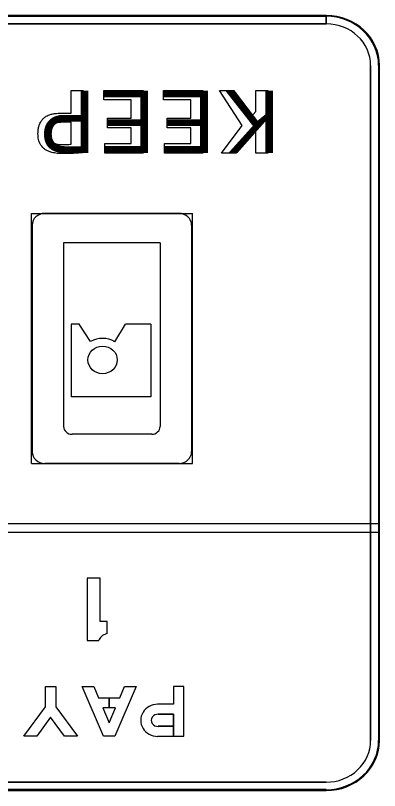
# Model space of a CAD drawing. Extents: x -102643 to -98250, y 54554 to 62384.
# Drawn here: x -101875 to -101631, y 61400 to 61919 of the extents above; entities that cross this region are included whole.
import ezdxf

# ---------------------------------------------------------------- set-up
doc = ezdxf.new("R2010")
doc.units = 0
for name, color, linetype in [('GSBWFill', 7, 'Continuous'), ('GSColorFill', 7, 'Continuous'), ('GSOutline', 7, 'Continuous'), ('SignPanel', 7, 'Continuous')]:
    doc.layers.add(name, color=color, linetype=linetype)

msp = doc.modelspace()

# ---------------------------------------------------------------- linework, layer by layer
at = {"layer": 'GSBWFill'}
for p, q in [((-101666.66, 61919), (-102149.4, 61919)), ((-101666.66, 61913.42), (-101666.66, 61919)), ((-101666.6, 61919), (-101666.6, 61913.42)), ((-102149.4, 61913.42), (-101666.66, 61913.42)), ((-101636.79, 61885.49), (-101636.79, 61433.02)), ((-101630.83, 61433.02), (-101630.83, 61885.49)), ((-101666.6, 61405.09), (-102149.4, 61405.09)), ((-102149.4, 61399.51), (-101666.6, 61399.51))]:
    msp.add_line(p, q, dxfattribs=at)
for centre, major_axis, start_param, end_param in [((-101666.6, 61885.49), (-35.76, 0), 3.141593, 4.712389), ((-101666.6, 61885.49), (-29.8, 0), 3.141593, 4.712389), ((-101666.6, 61433.02), (-35.76, 0), 1.570796, 3.141593), ((-101666.6, 61433.02), (-29.8, 0), 1.570796, 3.141593)]:
    msp.add_ellipse(centre, major_axis=major_axis, ratio=0.937161, start_param=start_param, end_param=end_param, dxfattribs=at)
at = {"layer": 'GSColorFill'}
for p, q in [((-101666.6, 61919), (-102149.4, 61919)), ((-101630.83, 61433.02), (-101630.83, 61885.49)), ((-102149.4, 61399.51), (-101666.6, 61399.51))]:
    msp.add_line(p, q, dxfattribs=at)
for centre, start_param, end_param in [((-101666.6, 61885.49), 3.141593, 4.712389), ((-101666.6, 61433.02), 1.570796, 3.141593)]:
    msp.add_ellipse(centre, major_axis=(-35.76, 0), ratio=0.937161, start_param=start_param, end_param=end_param, dxfattribs=at)
at = {"layer": 'GSOutline'}
for p, q in [((-101666.6, 61919), (-102149.4, 61919)), ((-101666.6, 61913.42), (-102149.4, 61913.42)), ((-101636.79, 61433.02), (-101636.79, 61885.49)), ((-101630.83, 61433.02), (-101630.83, 61885.49)), ((-102149.4, 61405.09), (-101666.6, 61405.09)), ((-102149.4, 61399.51), (-101666.6, 61399.51))]:
    msp.add_line(p, q, dxfattribs=at)
for centre, major_axis, start_param, end_param in [((-101666.6, 61885.49), (-35.76, 0), 3.141593, 4.712389), ((-101666.6, 61885.49), (-29.8, 0), 3.141593, 4.712389), ((-101666.6, 61433.02), (-35.76, 0), 1.570796, 3.141593), ((-101666.6, 61433.02), (-29.8, 0), 1.570796, 3.141593)]:
    msp.add_ellipse(centre, major_axis=major_axis, ratio=0.937161, start_param=start_param, end_param=end_param, dxfattribs=at)
at = {"layer": 'SignPanel'}
for p, q in [((-101666.66, 61919), (-102149.4, 61919)), ((-101666.6, 61919), (-102149.4, 61919)), ((-101666.66, 61913.42), (-101666.66, 61919)), ((-101666.6, 61919), (-101666.6, 61913.42)), ((-101666.6, 61919), (-101666.6, 61918.45)), ((-101666.6, 61918.45), (-101666.6, 61919)), ((-102149.4, 61918.45), (-101666.6, 61918.45)), ((-102149.4, 61913.42), (-101666.66, 61913.42)), ((-101636.79, 61885.49), (-101636.79, 61433.02)), ((-101631.43, 61885.49), (-101631.43, 61433.02)), ((-101630.83, 61433.02), (-101630.83, 61885.49)), ((-101630.83, 61433.02), (-101630.83, 61885.49)), ((-101864.48, 61618.76), (-101864.48, 61786.34)), ((-101864.48, 61786.34), (-101756.44, 61786.34)), ((-101765.4, 61786.34), (-101855.52, 61786.34)), ((-101756.44, 61618.76), (-101756.44, 61786.34)), ((-101863.97, 61778.45), (-101863.97, 61626.65)), ((-101756.96, 61778.45), (-101756.96, 61626.65)), ((-101778.08, 61766.61), (-101842.84, 61766.61)), ((-101842.84, 61766.61), (-101842.84, 61643.53)), ((-101778.08, 61766.61), (-101778.08, 61643.53)), ((-101832.18, 61712.04), (-101837.82, 61712.04)), ((-101837.82, 61712.04), (-101837.82, 61663.34)), ((-101824.76, 61700.44), (-101832.32, 61712.02)), ((-101808.47, 61700.34), (-101801.21, 61712.04)), ((-101784.31, 61712.04), (-101801.21, 61712.04)), ((-101784.31, 61712.04), (-101784.31, 61663.34)), ((-101784.31, 61663.34), (-101837.82, 61663.34)), ((-101783.71, 61638.27), (-101837.21, 61638.27)), ((-101864.48, 61618.76), (-101756.44, 61618.76)), ((-101765.4, 61618.76), (-101855.52, 61618.76)), ((-101630.83, 61578.26), (-102185.16, 61578.26)), ((-101630.83, 61578.26), (-102185.16, 61578.26)), ((-101630.83, 61578.26), (-102185.16, 61578.26)), ((-101630.83, 61572.67), (-101630.83, 61578.26)), ((-101630.83, 61572.67), (-101630.83, 61578.26)), ((-101630.83, 61572.67), (-101630.83, 61578.26)), ((-102185.16, 61572.67), (-101630.83, 61572.67)), ((-102185.16, 61572.67), (-101630.83, 61572.67)), ((-102185.16, 61572.67), (-101630.83, 61572.67)), ((-101769.14, 61457.29), (-101779.75, 61457.29)), ((-101769.14, 61450.59), (-101779.38, 61450.59)), ((-101666.6, 61405.09), (-102149.4, 61405.09)), ((-101666.6, 61400.07), (-102149.4, 61400.07)), ((-102149.4, 61399.51), (-101666.6, 61399.51)), ((-102149.4, 61399.51), (-101666.6, 61399.51))]:
    msp.add_line(p, q, dxfattribs=at)
for points in [[(-101845.32, 61853.46), (-101837.7, 61853.46), (-101837.7, 61868.73), (-101829.66, 61868.73), (-101829.66, 61827.1)], [(-101789.56, 61868.73), (-101789.56, 61826.83), (-101815.15, 61826.83), (-101815.15, 61833.25), (-101797.6, 61833.25), (-101797.6, 61843.79), (-101813.46, 61843.79), (-101813.46, 61850.25), (-101797.6, 61850.25), (-101797.6, 61862.47), (-101815.83, 61862.47), (-101815.83, 61868.73), (-101789.56, 61868.73)], [(-101749.46, 61868.73), (-101749.46, 61826.83), (-101775.05, 61826.83), (-101775.05, 61833.25), (-101757.5, 61833.25), (-101757.5, 61843.79), (-101773.36, 61843.79), (-101773.36, 61850.25), (-101757.5, 61850.25), (-101757.5, 61862.47), (-101775.73, 61862.47), (-101775.73, 61868.73), (-101749.46, 61868.73)], [(-101728.55, 61868.73), (-101717.32, 61850.63), (-101713.74, 61854.74), (-101713.83, 61868.73), (-101705.79, 61868.73), (-101705.79, 61826.83), (-101713.83, 61826.83), (-101713.74, 61845.31), (-101714.01, 61845.31), (-101727.21, 61826.83), (-101736.93, 61826.83), (-101722.96, 61845.23), (-101738.27, 61868.73), (-101728.55, 61868.73)], [(-101837.7, 61832.74), (-101837.7, 61847.4), (-101843.92, 61847.4)], [(-101813.64, 61504.72), (-101813.64, 61512.71), (-101818.23, 61512.71), (-101818.23, 61541.95), (-101827.05, 61541.95), (-101827.05, 61500.05), (-101819.29, 61500.05)], [(-101813.64, 61504.72), (-101813.64, 61512.71), (-101818.23, 61512.71), (-101818.23, 61541.95), (-101827.05, 61541.95), (-101827.05, 61500.05), (-101819.29, 61500.05)], [(-101813.64, 61504.72), (-101813.64, 61512.71), (-101818.23, 61512.71), (-101818.23, 61541.95), (-101827.05, 61541.95), (-101827.05, 61500.05), (-101819.29, 61500.05)], [(-101779.75, 61435.82), (-101762.08, 61435.82), (-101762.08, 61469.33), (-101769.14, 61469.33), (-101769.14, 61457.29)], [(-101762.08, 61435.82), (-101762.08, 61469.33), (-101769.14, 61469.33), (-101769.14, 61457.29), (-101779.75, 61457.29)], [(-101762.08, 61435.82), (-101762.08, 61469.33), (-101769.14, 61469.33), (-101769.14, 61457.29), (-101779.75, 61457.29)], [(-101779.38, 61442.52), (-101769.14, 61442.52), (-101769.14, 61450.59)], [(-101779.38, 61450.59), (-101769.14, 61450.59), (-101769.14, 61435.82), (-101762.08, 61435.82)], [(-101779.38, 61450.59), (-101769.14, 61450.59), (-101769.14, 61435.82), (-101762.08, 61435.82)], [(-101779.75, 61435.82), (-101769.14, 61435.82), (-101769.14, 61442.52), (-101779.38, 61442.52)], [(-101779.75, 61435.82), (-101769.14, 61435.82), (-101769.14, 61442.52), (-101779.38, 61442.52)]]:
    msp.add_lwpolyline(points, dxfattribs=at)
for points in [[(-101855.1, 61469.33), (-101847.95, 61469.33), (-101847.95, 61455.59), (-101833.47, 61435.82), (-101842.14, 61435.82), (-101851.53, 61448.63), (-101860.91, 61435.82), (-101869.59, 61435.82), (-101855.1, 61455.59)], [(-101855.1, 61469.33), (-101847.95, 61469.33), (-101847.95, 61455.59), (-101833.47, 61435.82), (-101842.14, 61435.82), (-101851.53, 61448.63), (-101860.91, 61435.82), (-101869.59, 61435.82), (-101855.1, 61455.59)], [(-101855.1, 61469.33), (-101847.95, 61469.33), (-101847.95, 61455.59), (-101833.47, 61435.82), (-101842.14, 61435.82), (-101851.53, 61448.63), (-101860.91, 61435.82), (-101869.59, 61435.82), (-101855.1, 61455.59)], [(-101819.35, 61461.62), (-101805.17, 61461.62), (-101801.9, 61469.33), (-101794.2, 61469.33), (-101808.41, 61435.82), (-101816.11, 61435.82), (-101830.32, 61469.33), (-101822.62, 61469.33)], [(-101812.26, 61454.92), (-101812.26, 61461.62), (-101805.17, 61461.62), (-101801.9, 61469.33), (-101794.2, 61469.33), (-101808.41, 61435.82), (-101816.11, 61435.82), (-101830.32, 61469.33), (-101822.62, 61469.33), (-101819.35, 61461.62), (-101812.26, 61461.62), (-101812.26, 61454.92), (-101816.51, 61454.92), (-101812.26, 61444.89), (-101808.01, 61454.92)], [(-101812.26, 61454.92), (-101812.26, 61461.62), (-101805.17, 61461.62), (-101801.9, 61469.33), (-101794.2, 61469.33), (-101808.41, 61435.82), (-101816.11, 61435.82), (-101830.32, 61469.33), (-101822.62, 61469.33), (-101819.35, 61461.62), (-101812.26, 61461.62), (-101812.26, 61454.92), (-101816.51, 61454.92), (-101812.26, 61444.89), (-101808.01, 61454.92)], [(-101808.01, 61454.92), (-101816.51, 61454.92), (-101812.26, 61444.89)]]:
    msp.add_lwpolyline(points, close=True, dxfattribs=at)
for centre, major_axis, ratio, start_param, end_param in [((-101666.6, 61885.49), (-35.76, 0), 0.937161, 3.141593, 4.712389), ((-101666.6, 61885.49), (-35.76, 0), 0.937161, 3.141593, 4.712389), ((-101666.6, 61885.49), (-35.17, 0), 0.937161, 3.141593, 4.712389), ((-101666.6, 61885.49), (-29.8, 0), 0.937161, 3.141593, 4.712389), ((-101855.52, 61778.45), (-8.45, 0), 0.933944, 4.712389, 6.283185), ((-101765.4, 61778.45), (8.45, 0), 0.933944, 0, 1.570796), ((-101816.7, 61688.09), (-15.49, 0), 0.933944, 4.152074, 5.259887), ((-101837.21, 61643.54), (5.63, 0), 0.933944, 3.141593, 4.712389), ((-101783.71, 61643.54), (5.63, 0), 0.933944, 4.712389, 6.283185), ((-101855.52, 61626.65), (8.45, 0), 0.933944, 3.141593, 4.712389), ((-101765.4, 61626.65), (8.45, 0), 0.933944, 4.712389, 6.283185), ((-101811.8, 61497.43), (-7.99, 0), 0.937165, 5.230245, 5.516697), ((-101811.8, 61497.43), (-7.99, 0), 0.937165, 5.230245, 5.516697), ((-101811.8, 61497.43), (-7.99, 0), 0.937165, 5.230245, 5.516697), ((-101811.8, 61497.43), (-7.99, 0), 0.937165, 4.943792, 5.230245), ((-101811.8, 61497.43), (-7.99, 0), 0.937165, 4.943792, 5.230245), ((-101811.8, 61497.43), (-7.99, 0), 0.937165, 4.943792, 5.230245), ((-101811.8, 61497.43), (-7.99, 0), 0.937165, 5.720992, 5.925287), ((-101811.8, 61497.43), (-7.99, 0), 0.937165, 5.720992, 5.925287), ((-101811.8, 61497.43), (-7.99, 0), 0.937165, 5.720992, 5.925287), ((-101811.8, 61497.43), (-7.99, 0), 0.937165, 5.516697, 5.720992), ((-101811.8, 61497.43), (-7.99, 0), 0.937165, 5.516697, 5.720992), ((-101811.8, 61497.43), (-7.99, 0), 0.937165, 5.516697, 5.720992), ((-101779.76, 61446.55), (-11.3, 0), 0.950592, 4.711784, 7.854587), ((-101779.76, 61446.55), (-11.3, 0), 0.950592, 4.711784, 7.854587), ((-101779.76, 61446.55), (-11.3, 0), 0.950592, 4.711784, 7.854587), ((-101779.74, 61446.55), (-4.26, 0), 0.950592, 4.627407, 7.938964), ((-101779.74, 61446.55), (-4.26, 0), 0.950592, 4.627407, 7.938964), ((-101779.74, 61446.55), (-4.26, 0), 0.950592, 4.627407, 7.938964), ((-101666.6, 61433.02), (-35.76, 0), 0.937161, 1.570796, 3.141593), ((-101666.6, 61433.02), (-29.8, 0), 0.937161, 1.570796, 3.141593), ((-101666.6, 61433.02), (-35.76, 0), 0.937161, 1.570796, 3.141593), ((-101666.6, 61433.02), (-35.17, 0), 0.937161, 1.570796, 3.141593)]:
    msp.add_ellipse(centre, major_axis=major_axis, ratio=ratio, start_param=start_param, end_param=end_param, dxfattribs=at)
msp.add_ellipse((-101816.7, 61688.09), major_axis=(-9.86, 0), ratio=0.933944, dxfattribs=at)
for points in [[(-101860.03, 61839.78), (-101860.02, 61840.31), (-101859.99, 61841.83), (-101859.67, 61844.01), (-101859.05, 61846.02), (-101858.4, 61847.41), (-101857.74, 61848.49), (-101857.1, 61849.32), (-101856.53, 61849.93), (-101855.93, 61850.5), (-101855.08, 61851.15), (-101853.93, 61851.82), (-101852.41, 61852.47), (-101850.17, 61853.1), (-101847.68, 61853.42), (-101845.94, 61853.45), (-101845.32, 61853.46)], [(-101843.92, 61847.4), (-101844.53, 61847.39), (-101845.43, 61847.37), (-101846.57, 61847.25), (-101847.23, 61847.16), (-101847.84, 61847.03), (-101848.4, 61846.86), (-101849.03, 61846.59), (-101849.51, 61846.3), (-101849.85, 61846.04), (-101850.18, 61845.75), (-101850.55, 61845.33), (-101850.92, 61844.76), (-101851.17, 61844.22), (-101851.39, 61843.61), (-101851.66, 61842.6), (-101851.8, 61841.3), (-101851.82, 61840.27), (-101851.82, 61839.9)], [(-101843.51, 61826.43), (-101844.09, 61826.43), (-101845.78, 61826.46), (-101847.99, 61826.68), (-101850.1, 61827.05), (-101851.34, 61827.37), (-101852.5, 61827.76), (-101853.59, 61828.21), (-101854.61, 61828.77), (-101855.36, 61829.27), (-101856.08, 61829.8), (-101856.91, 61830.56), (-101857.77, 61831.6), (-101858.38, 61832.57), (-101858.81, 61833.4), (-101859.2, 61834.3), (-101859.67, 61835.8), (-101859.98, 61837.73), (-101860.01, 61839.17), (-101860.03, 61839.78)], [(-101851.82, 61839.9), (-101851.82, 61839.56), (-101851.81, 61838.63), (-101851.67, 61837.45), (-101851.45, 61836.5), (-101851.26, 61835.92), (-101851.03, 61835.39), (-101850.69, 61834.8), (-101850.34, 61834.37), (-101850.03, 61834.07), (-101849.7, 61833.78), (-101849.23, 61833.46), (-101848.6, 61833.15), (-101848.03, 61832.94), (-101847.4, 61832.77), (-101846.39, 61832.57), (-101845.13, 61832.45), (-101844.14, 61832.44), (-101843.79, 61832.43)], [(-101843.79, 61832.43), (-101843.31, 61832.44), (-101842.35, 61832.45), (-101840.87, 61832.52), (-101839.32, 61832.62), (-101838.26, 61832.7), (-101837.7, 61832.74)], [(-101829.66, 61827.1), (-101830.69, 61827), (-101832.85, 61826.81), (-101836.21, 61826.6), (-101839.79, 61826.45), (-101842.25, 61826.44), (-101843.51, 61826.43)]]:
    msp.add_open_spline(points, degree=3, dxfattribs=at)

# ---------------------------------------------------------------- texts
for s, p in [('P', (-101821.62, 61868.73)), ('P', (-101821.62, 61868.73)), ('E', (-101781.52, 61868.73)), ('E', (-101781.52, 61868.73)), ('E', (-101741.42, 61868.73)), ('E', (-101741.42, 61868.73)), ('K', (-101697.75, 61868.73)), ('K', (-101697.75, 61868.73))]:
    msp.add_text(s, height=41.89, rotation=180, dxfattribs=at).set_placement(p)

doc.saveas('drawing.dxf')
